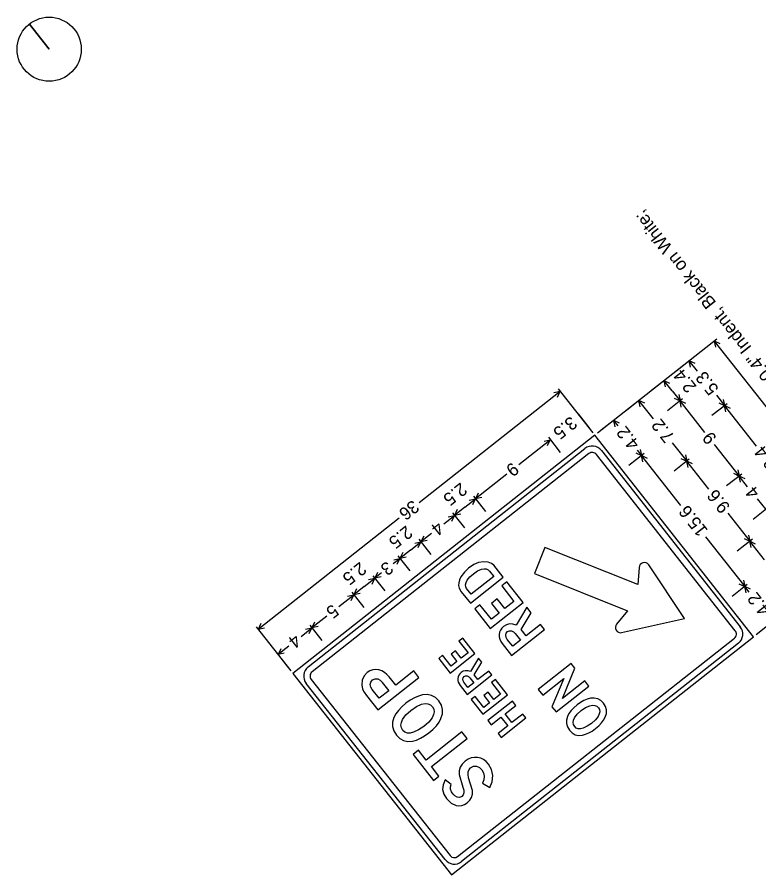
# Model space of a CAD drawing. Extents: x 672438 to 673696, y 1673540 to 1674850.
# Drawn here: x 672585.4 to 672638.3, y 1674789.1 to 1674850.3 of the extents above; entities that cross this region are included whole.
import ezdxf

# ---------------------------------------------------------------- set-up
doc = ezdxf.new("R2010")
doc.units = 0
doc.layers.add('C-TABL-BORD', color=7, linetype='Continuous')

msp = doc.modelspace()

# ---------------------------------------------------------------- linework, layer by layer
at = {"layer": 'C-TABL-BORD'}
for p, q in [((672586.309, 1674849.76), (672587.724, 1674847.964)), ((672587.724, 1674847.964), (672586.309, 1674849.76)), ((672635.358, 1674827.298), (672626.831, 1674820.575)), ((672640.275, 1674820.692), (672635.179, 1674827.156)), ((672635.593, 1674826.961), (672635.179, 1674827.156)), ((672635.272, 1674826.708), (672635.179, 1674827.156)), ((672633.563, 1674825.882), (672632.486, 1674825.033)), ((672633.968, 1674825), (672633.384, 1674825.741)), ((672633.797, 1674825.546), (672633.384, 1674825.741)), ((672633.476, 1674825.293), (672633.384, 1674825.741)), ((672631.768, 1674824.467), (672630.691, 1674823.618)), ((672632.156, 1674823.605), (672631.588, 1674824.326)), ((672632.002, 1674824.131), (672631.588, 1674824.326)), ((672631.681, 1674823.878), (672631.588, 1674824.326)), ((672614.118, 1674815.648), (672624.175, 1674823.575)), ((672623.727, 1674823.482), (672624.175, 1674823.575)), ((672623.98, 1674823.162), (672624.175, 1674823.575)), ((672624.033, 1674823.755), (672626.51, 1674820.613)), ((672632.156, 1674823.605), (672632.725, 1674822.884)), ((672632.632, 1674823.332), (672632.725, 1674822.884)), ((672629.973, 1674823.052), (672628.895, 1674822.203)), ((672630.83, 1674821.596), (672629.793, 1674822.91)), ((672630.207, 1674822.716), (672629.793, 1674822.91)), ((672629.886, 1674822.463), (672629.793, 1674822.91)), ((672632.904, 1674823.026), (672631.827, 1674822.176)), ((672632.904, 1674823.026), (672631.827, 1674822.176)), ((672632.311, 1674823.079), (672632.725, 1674822.884)), ((672634.502, 1674820.629), (672632.725, 1674822.884)), ((672633.138, 1674822.69), (672632.725, 1674822.884)), ((672632.817, 1674822.437), (672632.725, 1674822.884)), ((672635.318, 1674823.287), (672635.902, 1674822.546)), ((672635.488, 1674822.741), (672635.902, 1674822.546)), ((672635.809, 1674822.994), (672635.902, 1674822.546)), ((672636.082, 1674822.688), (672635.005, 1674821.838)), ((672636.082, 1674822.688), (672635.005, 1674821.838)), ((672638.171, 1674819.668), (672635.902, 1674822.546)), ((672636.316, 1674822.351), (672635.902, 1674822.546)), ((672635.995, 1674822.098), (672635.902, 1674822.546)), ((672625.448, 1674821.96), (672626.298, 1674820.883)), ((672628.177, 1674821.637), (672627.1, 1674820.788)), ((672628.306, 1674821.104), (672627.998, 1674821.495)), ((672628.412, 1674821.3), (672627.998, 1674821.495)), ((672628.091, 1674821.047), (672627.998, 1674821.495)), ((672623.331, 1674820.29), (672624.18, 1674819.213)), ((672623.331, 1674820.29), (672624.18, 1674819.213)), ((672621.226, 1674818.34), (672623.472, 1674820.111)), ((672623.024, 1674820.018), (672623.472, 1674820.111)), ((672623.277, 1674819.697), (672623.472, 1674820.111)), ((672632.167, 1674819.899), (672633.204, 1674818.584)), ((672635.171, 1674819.781), (672636.948, 1674817.527)), ((672630.159, 1674819.123), (672629.082, 1674818.274)), ((672630.159, 1674819.123), (672629.082, 1674818.274)), ((672629.566, 1674819.177), (672629.979, 1674818.982)), ((672629.671, 1674819.373), (672629.979, 1674818.982)), ((672629.886, 1674819.43), (672629.979, 1674818.982)), ((672633.111, 1674819.032), (672633.204, 1674818.584)), ((672632.781, 1674815.428), (672629.979, 1674818.982)), ((672630.393, 1674818.787), (672629.979, 1674818.982)), ((672630.072, 1674818.534), (672629.979, 1674818.982)), ((672633.383, 1674818.725), (672632.306, 1674817.876)), ((672633.383, 1674818.725), (672632.306, 1674817.876)), ((672632.79, 1674818.779), (672633.204, 1674818.584)), ((672634.776, 1674816.589), (672633.204, 1674818.584)), ((672633.618, 1674818.389), (672633.204, 1674818.584)), ((672633.297, 1674818.136), (672633.204, 1674818.584)), ((672636.856, 1674817.974), (672636.948, 1674817.527)), ((672620.379, 1674817.672), (672618.133, 1674815.902)), ((672637.128, 1674817.668), (672636.051, 1674816.819)), ((672636.535, 1674817.721), (672636.948, 1674817.527)), ((672637.548, 1674816.767), (672636.948, 1674817.527)), ((672637.362, 1674817.332), (672636.948, 1674817.527)), ((672637.041, 1674817.079), (672636.948, 1674817.527)), ((672617.992, 1674816.081), (672618.841, 1674815.004)), ((672618.328, 1674816.315), (672618.133, 1674815.902)), ((672618.581, 1674815.995), (672618.133, 1674815.902)), ((672617.385, 1674815.312), (672618.133, 1674815.902)), ((672617.685, 1674815.809), (672618.133, 1674815.902)), ((672617.938, 1674815.488), (672618.133, 1674815.902)), ((672638.237, 1674815.892), (672638.835, 1674815.133)), ((672616.496, 1674814.902), (672617.345, 1674813.825)), ((672617.385, 1674815.312), (672616.637, 1674814.722)), ((672616.832, 1674815.136), (672616.637, 1674814.722)), ((672617.085, 1674814.815), (672616.637, 1674814.722)), ((672636.132, 1674814.87), (672637.704, 1674812.875)), ((672639.015, 1674815.274), (672637.938, 1674814.425)), ((672612.688, 1674814.52), (672602.632, 1674806.592)), ((672615.877, 1674814.123), (672616.637, 1674814.722)), ((672616.189, 1674814.629), (672616.637, 1674814.722)), ((672616.442, 1674814.308), (672616.637, 1674814.722)), ((672614.102, 1674813.015), (672614.951, 1674811.938)), ((672615.004, 1674813.434), (672614.244, 1674812.835)), ((672614.439, 1674813.249), (672614.244, 1674812.835)), ((672614.691, 1674812.928), (672614.244, 1674812.835)), ((672634.537, 1674813.201), (672637.339, 1674809.647)), ((672637.884, 1674813.017), (672636.807, 1674812.168)), ((672637.291, 1674813.07), (672637.704, 1674812.875)), ((672637.611, 1674813.323), (672637.704, 1674812.875)), ((672646.68, 1674812.936), (672638.153, 1674806.213)), ((672613.496, 1674812.245), (672614.244, 1674812.835)), ((672613.796, 1674812.742), (672614.244, 1674812.835)), ((672614.049, 1674812.421), (672614.244, 1674812.835)), ((672638.741, 1674811.56), (672637.704, 1674812.875)), ((672638.118, 1674812.68), (672637.704, 1674812.875)), ((672637.797, 1674812.427), (672637.704, 1674812.875)), ((672612.606, 1674811.835), (672613.455, 1674810.758)), ((672613.496, 1674812.245), (672612.748, 1674811.656)), ((672612.942, 1674812.069), (672612.748, 1674811.656)), ((672613.195, 1674811.749), (672612.748, 1674811.656)), ((672612.272, 1674811.281), (672612.748, 1674811.656)), ((672612.3, 1674811.563), (672612.748, 1674811.656)), ((672612.553, 1674811.242), (672612.748, 1674811.656)), ((672611.147, 1674810.654), (672610.952, 1674810.241)), ((672611.428, 1674810.616), (672610.952, 1674810.241)), ((672610.204, 1674809.651), (672610.952, 1674810.241)), ((672610.505, 1674810.148), (672610.952, 1674810.241)), ((672610.757, 1674809.827), (672610.952, 1674810.241)), ((672610.811, 1674810.42), (672611.66, 1674809.343)), ((672611.4, 1674810.333), (672610.952, 1674810.241)), ((672637.246, 1674810.094), (672637.339, 1674809.647)), ((672609.315, 1674809.241), (672610.164, 1674808.164)), ((672610.204, 1674809.651), (672609.456, 1674809.061)), ((672609.651, 1674809.475), (672609.456, 1674809.061)), ((672637.518, 1674809.788), (672636.441, 1674808.939)), ((672636.925, 1674809.842), (672637.339, 1674809.647)), ((672637.647, 1674809.256), (672637.339, 1674809.647)), ((672637.752, 1674809.452), (672637.339, 1674809.647)), ((672637.432, 1674809.199), (672637.339, 1674809.647)), ((672608.386, 1674808.217), (672609.456, 1674809.061)), ((672609.009, 1674808.968), (672609.456, 1674809.061)), ((672609.261, 1674808.647), (672609.456, 1674809.061)), ((672609.904, 1674809.154), (672609.456, 1674809.061)), ((672607.534, 1674807.546), (672606.464, 1674806.702)), ((672602.827, 1674807.006), (672602.632, 1674806.592)), ((672606.323, 1674806.882), (672607.172, 1674805.805)), ((672606.659, 1674807.116), (672606.464, 1674806.702)), ((672606.912, 1674806.795), (672606.464, 1674806.702)), ((672602.491, 1674806.772), (672604.967, 1674803.63)), ((672603.08, 1674806.685), (672602.632, 1674806.592)), ((672605.693, 1674806.094), (672606.464, 1674806.702)), ((672606.017, 1674806.609), (672606.464, 1674806.702)), ((672606.269, 1674806.289), (672606.464, 1674806.702)), ((672603.906, 1674804.976), (672604.755, 1674803.899)), ((672604.819, 1674805.405), (672604.047, 1674804.797)), ((672604.242, 1674805.211), (672604.047, 1674804.797)), ((672604.495, 1674804.89), (672604.047, 1674804.797))]:
    msp.add_line(p, q, dxfattribs=at)
for points in [[(672637.974, 1674806.072), (672626.651, 1674820.434), (672605.109, 1674803.451), (672616.431, 1674789.089), (672637.974, 1674806.072), (672637.974, 1674806.072)], [(672606.195, 1674803.919), (672625.943, 1674819.487)], [(672626.226, 1674819.128), (672606.478, 1674803.56)], [(672636.668, 1674806.498), (672626.761, 1674819.064)], [(672627.12, 1674819.347), (672637.027, 1674806.781)], [(672629.712, 1674809.784), (672623.074, 1674812.433), (672622.333, 1674810.575)], [(672617.122, 1674809.279), (672617.771, 1674808.456), (672620.118, 1674810.307), (672619.439, 1674811.168), (672619.28, 1674811.298), (672619.039, 1674811.386), (672618.704, 1674811.418), (672618.358, 1674811.359), (672618.006, 1674811.208), (672617.646, 1674810.967), (672617.34, 1674810.676), (672617.099, 1674810.337), (672616.997, 1674810.12), (672616.94, 1674809.915), (672616.931, 1674809.723), (672616.968, 1674809.542), (672617.122, 1674809.279)], [(672633.054, 1674807.374), (672630.494, 1674811.204)], [(672619.142, 1674810.751), (672619.442, 1674810.37), (672617.832, 1674809.101), (672617.505, 1674809.517), (672617.441, 1674809.637), (672617.426, 1674809.774), (672617.46, 1674809.925), (672617.543, 1674810.092), (672617.731, 1674810.333), (672617.984, 1674810.564), (672618.274, 1674810.756), (672618.563, 1674810.877), (672618.746, 1674810.913), (672618.903, 1674810.904), (672619.035, 1674810.849), (672619.142, 1674810.751)], [(672622.333, 1674810.575), (672622.333, 1674810.575), (672628.97, 1674807.926)], [(672629.806, 1674811.009), (672629.712, 1674809.784)], [(672623.059, 1674806.577), (672622.769, 1674806.945), (672621.739, 1674806.133), (672621.385, 1674806.582), (672622.112, 1674807.777), (672621.79, 1674808.186), (672621.025, 1674806.904), (672620.805, 1674806.974), (672620.569, 1674806.98), (672620.343, 1674806.924), (672620.143, 1674806.808), (672620.015, 1674806.686), (672619.92, 1674806.548), (672619.858, 1674806.395), (672619.829, 1674806.227), (672619.833, 1674806.056), (672619.869, 1674805.89), (672619.938, 1674805.732), (672620.038, 1674805.58), (672620.713, 1674804.728), (672623.059, 1674806.577)], [(672628.97, 1674807.926), (672628.196, 1674806.974)], [(672628.561, 1674806.359), (672633.054, 1674807.374), (672633.054, 1674807.374)], [(672621.342, 1674805.82), (672620.789, 1674805.384), (672620.403, 1674805.874), (672620.32, 1674806.018), (672620.29, 1674806.172), (672620.319, 1674806.316), (672620.414, 1674806.432), (672620.557, 1674806.499), (672620.713, 1674806.488), (672620.851, 1674806.415), (672620.971, 1674806.29), (672621.342, 1674805.82)], [(672616.857, 1674790.395), (672636.604, 1674805.963)], [(672636.887, 1674805.604), (672617.14, 1674790.036)], [(672619.3, 1674803.344), (672619.083, 1674803.62), (672618.31, 1674803.011), (672618.045, 1674803.348), (672618.591, 1674804.244), (672618.349, 1674804.551), (672617.775, 1674803.59), (672617.61, 1674803.642), (672617.433, 1674803.647), (672617.263, 1674803.604), (672617.114, 1674803.517), (672617.018, 1674803.426), (672616.946, 1674803.322), (672616.9, 1674803.208), (672616.878, 1674803.082), (672616.881, 1674802.953), (672616.908, 1674802.829), (672616.96, 1674802.711), (672617.035, 1674802.597), (672617.541, 1674801.957), (672619.3, 1674803.344)], [(672614.103, 1674803.167), (672613.74, 1674803.627), (672612.448, 1674802.608), (672611.976, 1674803.207), (672611.813, 1674803.386), (672611.636, 1674803.529), (672611.446, 1674803.635), (672611.239, 1674803.702), (672611.016, 1674803.73), (672610.801, 1674803.708), (672610.596, 1674803.634), (672610.399, 1674803.509), (672610.185, 1674803.275), (672610.055, 1674802.975), (672610.018, 1674802.649), (672610.08, 1674802.331), (672610.184, 1674802.126), (672610.371, 1674801.866), (672611.169, 1674800.854), (672614.103, 1674803.167)], [(672618.012, 1674802.776), (672617.598, 1674802.45), (672617.309, 1674802.817), (672617.246, 1674802.925), (672617.224, 1674803.04), (672617.246, 1674803.149), (672617.316, 1674803.235), (672617.424, 1674803.286), (672617.541, 1674803.277), (672617.645, 1674803.223), (672617.734, 1674803.129), (672618.012, 1674802.776)], [(672615.963, 1674790.175), (672606.056, 1674802.742)], [(672606.415, 1674803.025), (672616.322, 1674790.458)], [(672611.957, 1674802.221), (672611.266, 1674801.677), (672610.768, 1674802.308), (672610.669, 1674802.481), (672610.633, 1674802.659), (672610.674, 1674802.839), (672610.797, 1674802.986), (672610.98, 1674803.076), (672611.17, 1674803.067), (672611.334, 1674802.979), (672611.481, 1674802.824), (672611.488, 1674802.815), (672611.957, 1674802.221)], [(672613.172, 1674801.327), (672612.876, 1674801.072), (672612.633, 1674800.815), (672612.445, 1674800.559), (672612.308, 1674800.301), (672612.216, 1674799.978), (672612.215, 1674799.662), (672612.307, 1674799.356), (672612.49, 1674799.058), (672612.73, 1674798.82), (672613.001, 1674798.669), (672613.307, 1674798.606), (672613.645, 1674798.629), (672613.926, 1674798.703), (672614.213, 1674798.824), (672614.508, 1674798.994), (672614.808, 1674799.211), (672615.1, 1674799.461), (672615.342, 1674799.714), (672615.532, 1674799.969), (672615.673, 1674800.228), (672615.78, 1674800.559), (672615.79, 1674800.88), (672615.704, 1674801.188), (672615.521, 1674801.486), (672615.283, 1674801.724), (672615.008, 1674801.874), (672614.698, 1674801.939), (672614.352, 1674801.916), (672614.066, 1674801.84), (672613.774, 1674801.716), (672613.476, 1674801.545), (672613.172, 1674801.327)], [(672613.524, 1674800.81), (672613.922, 1674801.082), (672614.291, 1674801.248), (672614.533, 1674801.297), (672614.743, 1674801.283), (672614.923, 1674801.207), (672615.07, 1674801.07), (672615.164, 1674800.901), (672615.19, 1674800.716), (672615.149, 1674800.514), (672615.04, 1674800.297), (672614.798, 1674799.988), (672614.454, 1674799.678), (672614.077, 1674799.42), (672613.719, 1674799.255), (672613.479, 1674799.197), (672613.273, 1674799.2), (672613.1, 1674799.264), (672612.961, 1674799.388), (672612.859, 1674799.566), (672612.819, 1674799.757), (672612.846, 1674799.959), (672612.936, 1674800.175), (672613.172, 1674800.489), (672613.524, 1674800.81)], [(672625.384, 1674801.21), (672625.148, 1674801.006), (672624.954, 1674800.8), (672624.803, 1674800.595), (672624.694, 1674800.389), (672624.62, 1674800.13), (672624.619, 1674799.878), (672624.693, 1674799.633), (672624.839, 1674799.395), (672625.031, 1674799.204), (672625.248, 1674799.084), (672625.492, 1674799.033), (672625.763, 1674799.052), (672625.988, 1674799.111), (672626.217, 1674799.208), (672626.453, 1674799.343), (672626.693, 1674799.517), (672626.927, 1674799.717), (672627.12, 1674799.919), (672627.273, 1674800.124), (672627.385, 1674800.33), (672627.471, 1674800.596), (672627.479, 1674800.852), (672627.41, 1674801.098), (672627.264, 1674801.337), (672627.073, 1674801.527), (672626.854, 1674801.648), (672626.605, 1674801.699), (672626.328, 1674801.681), (672626.1, 1674801.62), (672625.866, 1674801.521), (672625.628, 1674801.384), (672625.384, 1674801.21)], [(672625.666, 1674800.797), (672625.985, 1674801.014), (672626.28, 1674801.146), (672626.473, 1674801.186), (672626.641, 1674801.175), (672626.785, 1674801.114), (672626.903, 1674801.004), (672626.978, 1674800.869), (672626.999, 1674800.721), (672626.966, 1674800.56), (672626.879, 1674800.386), (672626.686, 1674800.139), (672626.41, 1674799.891), (672626.109, 1674799.684), (672625.822, 1674799.553), (672625.63, 1674799.505), (672625.465, 1674799.508), (672625.327, 1674799.559), (672625.216, 1674799.659), (672625.134, 1674799.801), (672625.102, 1674799.953), (672625.124, 1674800.116), (672625.196, 1674800.288), (672625.384, 1674800.54), (672625.666, 1674800.797)]]:
    msp.add_lwpolyline(points, dxfattribs=at)
for points in [[(672621.532, 1674808.513), (672620.375, 1674809.981), (672620.007, 1674809.691), (672620.877, 1674808.588), (672620.232, 1674808.08), (672619.684, 1674808.776), (672619.269, 1674808.449), (672619.818, 1674807.753), (672619.265, 1674807.317), (672618.456, 1674808.344), (672618.088, 1674808.054), (672619.185, 1674806.662)], [(672618.097, 1674804.87), (672617.229, 1674805.971), (672616.953, 1674805.753), (672617.606, 1674804.926), (672617.122, 1674804.545), (672616.711, 1674805.067), (672616.4, 1674804.822), (672616.812, 1674804.3), (672616.397, 1674803.973), (672615.79, 1674804.743), (672615.514, 1674804.526), (672616.337, 1674803.482)], [(672626.229, 1674802.555), (672625.939, 1674802.924), (672624.336, 1674801.66), (672625.223, 1674803.831), (672624.96, 1674804.165), (672622.613, 1674802.314), (672622.938, 1674801.902), (672624.431, 1674803.079), (672623.591, 1674801.073), (672623.881, 1674800.705)], [(672620.418, 1674801.926), (672619.55, 1674803.027), (672619.274, 1674802.809), (672619.927, 1674801.982), (672619.443, 1674801.601), (672619.032, 1674802.123), (672618.721, 1674801.878), (672619.133, 1674801.356), (672618.718, 1674801.029), (672618.111, 1674801.799), (672617.835, 1674801.581), (672618.658, 1674800.538)], [(672621.72, 1674800.274), (672621.503, 1674800.55), (672620.73, 1674799.941), (672620.24, 1674800.563), (672621.013, 1674801.172), (672620.769, 1674801.481), (672619.008, 1674800.093), (672619.252, 1674799.784), (672619.953, 1674800.336), (672620.443, 1674799.715), (672619.742, 1674799.162), (672619.96, 1674798.886)], [(672617.534, 1674798.814), (672617.166, 1674799.282), (672614.621, 1674797.276), (672614.074, 1674797.969), (672613.685, 1674797.662), (672615.132, 1674795.827), (672615.521, 1674796.134), (672614.989, 1674796.808)], [(672619.162, 1674795.317), (672619.334, 1674795.732), (672619.374, 1674796.175), (672619.285, 1674796.606), (672619.065, 1674796.991), (672618.896, 1674797.173), (672618.709, 1674797.312), (672618.505, 1674797.408), (672618.281, 1674797.459), (672618.053, 1674797.465), (672617.831, 1674797.424), (672617.616, 1674797.333), (672617.407, 1674797.196), (672617.194, 1674796.99), (672617.049, 1674796.764), (672616.973, 1674796.515), (672616.962, 1674796.246), (672617.237, 1674795.344), (672617.293, 1674795.123), (672617.297, 1674794.937), (672617.251, 1674794.788), (672617.153, 1674794.673), (672616.998, 1674794.605), (672616.818, 1674794.629), (672616.666, 1674794.712), (672616.534, 1674794.843), (672616.422, 1674795.02), (672616.363, 1674795.195), (672616.36, 1674795.367), (672616.41, 1674795.537), (672615.961, 1674795.859), (672615.817, 1674795.515), (672615.787, 1674795.179), (672615.869, 1674794.849), (672616.064, 1674794.525), (672616.393, 1674794.203), (672616.75, 1674794.029), (672616.957, 1674794.003), (672617.157, 1674794.026), (672617.353, 1674794.1), (672617.544, 1674794.224), (672617.73, 1674794.407), (672617.853, 1674794.616), (672617.913, 1674794.848), (672617.91, 1674795.107), (672617.644, 1674796.011), (672617.604, 1674796.239), (672617.614, 1674796.433), (672617.676, 1674796.593), (672617.789, 1674796.72), (672617.999, 1674796.83), (672618.213, 1674796.835), (672618.418, 1674796.747), (672618.596, 1674796.579), (672618.715, 1674796.365), (672618.762, 1674796.117), (672618.738, 1674795.862), (672618.643, 1674795.632)]]:
    msp.add_lwpolyline(points, close=True, dxfattribs=at)
msp.add_circle((672587.724, 1674847.964), 2.286, dxfattribs=at)
for centre, radius, start, end in [((672626.461, 1674818.828), 0.838, 38.2506, 128.25081), ((672626.461, 1674818.828), 0.381, 38.2506, 128.25081), ((672630.185, 1674810.98), 0.381, 35.97481, 175.62812), ((672628.491, 1674806.734), 0.381, 140.87286, 280.52611), ((672636.368, 1674806.262), 0.381, 308.25039, 38.2506), ((672636.368, 1674806.262), 0.838, 308.25039, 38.2506), ((672606.714, 1674803.261), 0.838, 128.25054, 218.25075), ((672606.714, 1674803.261), 0.381, 128.25054, 218.25075), ((672616.621, 1674790.694), 0.381, 218.25075, 308.25039), ((672616.621, 1674790.694), 0.838, 218.25075, 308.25039)]:
    msp.add_arc(centre, radius, start, end, dxfattribs=at)

# ---------------------------------------------------------------- texts
for s, height, rotation, p in [('1.5" Radius, 0.6" Border, 0.4" Indent, Black on White; ', 0.9144, 128.25054, (672647.937, 1674813.927)), ('2.4', 0.9144, 128.25054, (672633.951, 1674823.913)), ('5.3', 0.9144, 128.25054, (672635.535, 1674823.75)), ('3.5', 0.9144, 218.25075, (672624.925, 1674821.838)), ('7.2', 0.9144, 128.25054, (672632.385, 1674820.361)), ('4.2', 0.9144, 128.25054, (672629.889, 1674819.835)), ('9', 0.914, 128.25054, (672635.388, 1674820.244)), ('13.4', 0.9144, 128.25054, (672640.136, 1674817.914)), ('9', 0.914, 218.25075, (672620.764, 1674818.558)), ('2.5', 0.9144, 218.25075, (672617.079, 1674817.108)), ('4', 0.914, 128.25054, (672638.454, 1674816.355)), ('9.6', 0.9144, 128.25054, (672636.35, 1674815.332)), ('36', 0.9144, 218.25075, (672613.656, 1674815.865)), ('15.6', 0.9144, 128.25054, (672634.754, 1674813.663)), ('4', 0.914, 218.25075, (672615.415, 1674814.341)), ('2.5', 0.9144, 218.25075, (672613.189, 1674814.041)), ('2.5', 0.9144, 218.25075, (672609.898, 1674811.447)), ('3', 0.914, 218.25075, (672611.809, 1674811.498)), ('4.2', 0.9144, 128.25054, (672639.229, 1674807.987)), ('5', 0.914, 218.25075, (672607.923, 1674808.435)), ('4', 0.914, 218.25075, (672605.23, 1674806.312))]:
    msp.add_text(s, height=height, rotation=rotation, dxfattribs=at).set_placement(p)

doc.saveas('drawing.dxf')
